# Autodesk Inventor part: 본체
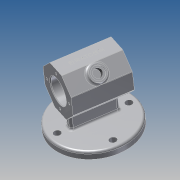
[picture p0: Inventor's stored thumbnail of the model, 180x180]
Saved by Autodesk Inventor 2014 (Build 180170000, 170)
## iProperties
Created: 2021-02
Part Number: 본체
Material: 알루미늄 6061
Document SubType Name: Modeling
Designer: kb542-22
Density: 2.71 g/cm^3
Appearance: 알루미늄 - 평지
Mass: 558.374 g
Surface Area: 514.422 cm^2
Volume: 206.042 cm^3
Author: kb542-22
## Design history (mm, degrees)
sketch "스케치1" dims "d9" = 58
  geometry: L1 (29, -12.012)-(12.012, -29); L2 (12.012, -29)-(-12.012, -29); L3 (-12.012, -29)-(-29, -12.012); L4 (-29, -12.012)-(-29, 12.012); L5 (-29, 12.012)-(-12.012, 29); L6 (-12.012, 29)-(12.012, 29); L7 (12.012, 29)-(29, 12.012); L8 (29, 12.012)-(29, -12.012); 4 further points
  constraints: 16 end point, 2 vertical alignment, 1 coincident, 1 horizontal alignment, 1 midpoint, 1 vertical, 20 other
extrude "돌출1" new body sketch "스케치1" stored distance "d10" = 70; taper "d11" = 0 deg
sketch "스케치2"
  geometry: L1 (12.012, 35)-(12.012, -35) reference; L2 (-12.012, 35)-(12.012, 35) reference; L3 (-12.012, 35)-(-12.012, -35) reference; L4 (12.012, -35)-(-12.012, -35) reference; L5 (0, 35)-(0, -35); L6 (0, 35)-(16, 35); L7 (16, 35)-(16, 23.3); L8 (15.7, 23)-(14, 23); L9 (14, 23)-(14, 20); L10 (14, 20)-(22, 20); L11 (22, 20)-(22, -20); L12 (22, -20)-(14, -20); L13 (14, -20)-(14, -23); L14 (14, -23)-(15.7, -23); L15 (16, -23.3)-(16, -35); L16 (16, -35)-(0, -35); A1 r 0.3 centre (15.7, 23.3) between (15.7, 23) and (16, 23.3); A2 r 0.3 centre (15.7, -23.3) between (16, -23.3) and (15.7, -23); 2 further points
  constraints: 24 end point, 6 perpendicular, 4 parallel, 4 point on circle, 4 tangent, 3 point on line, 2 centre point, 2 midpoint, 1 collinear, 1 equal radius
  dimensions: "d12" = 12 distance from line of point (16, 23) L6; "d13" = 12 distance between parallel lines of L16 L14; "d14" = 28 diameter of L9 L5; "d15" = 44 diameter of L11 L5; "d16" = 32 diameter of L7 L5; "d17" = 28 diameter of L13 L5; "d18" = 32 diameter of L15 L5; "d19" = 40 distance between parallel lines of L12 L10; "d20" = 3 distance between parallel lines of L10 L8 (derived); "d21" = 0.3 radius of A1
revolve "회전1" sketch "스케치2" stored, may be unused: angle "d22" = 90 deg
sketch "스케치3" dims "d23" = 46
  geometry: C1 r 16 at (0, 0) reference; 2 further points
  constraints: 2 vertical alignment, 1 coincident, 2 other
hole "구멍1" sketch "스케치3" at (0, 23) diameter "d24" = 3.242; stored, may be unused: countersink angle "d28" = 90 deg, drill point angle "d30" = 118 deg; dims "d25" = 8, "d26" = 4, "d27" = 2, "d29" = 10
sketch "스케치4"
  geometry: L1 (0, 0)-(0, 44.719); L2 (0, 0)-(24.042, 24.042); L3 (12.012, 29)-(29, 12.012) reference; C1 r 16 at (0, 0) reference; 1 further point
  constraints: 4 end point, 1 vertical
  dimensions: "d34" = 45 deg angle of L2 L1; "d35" = 5 distance from line of L3 L2.end
node "작업 평면1"
sketch "스케치5"
  geometry: C1 r 10 at (0, 0); 1 further point
  constraints: 1 centre point, 1 coincident
  dimensions: "d36" = 20 diameter of C1
extrude "돌출2" join sketch "스케치5" stored distance "d37" = 70; taper "d38" = 0 deg
node "작업 평면2"
sketch "스케치6"
  geometry: L1 (-29, 35)-(-29, -35) reference; L2 (29, 35)-(29, -35) reference; L3 (12.012, -35)-(-12.012, -35) reference; L4 (-12.012, 35)-(12.012, 35) reference; C1 r 52 at (0, 0); C2 r 4.5 at (-41, 0); C3 r 4.5 at (0, 41); C4 r 4.5 at (0, -41); C5 r 4.5 at (41, 0); A1 r 41 centre (0, 0) between (-41, 0) and (0, 41); 1 further point
  constraints: 6 centre point, 4 point on circle, 3 equal radius, 2 coincident, 2 horizontal alignment, 2 vertical alignment
  dimensions: "d40" = 104 diameter of C1; "d41" = 82 diameter of A1; "d42" = 9 diameter of C4
extrude "돌출3" join sketch "스케치6" distance "d43" = 10; taper "d44" = 0 deg
sketch "스케치7"
  geometry: L1 (28, -5)-(-28, -5); L2 (-28, -5)-(-28, 5); L3 (-28, 5)-(28, 5); L4 (28, 5)-(28, -5); L5 (-35, 12.012)-(35, 12.012) reference; L6 (-35, -12.012)-(-35, 12.012) reference; L7 (35, -12.012)-(-35, -12.012) reference; L8 (35, 12.012)-(35, -12.012) reference; C1 r 52 at (0, 0) reference; 2 further points
  constraints: 8 end point, 2 midpoint, 2 parallel, 1 horizontal, 1 horizontal alignment, 1 perpendicular, 1 vertical alignment
  dimensions: "d45" = 10 distance between parallel lines of L3 L1; "d46" = 56 distance between parallel lines of L4 L2
extrude "돌출4" join sketch "스케치7" stored distance "d47" = 10; taper "d48" = 0 deg
hole "구멍2" diameter "d51" = 10.917; stored, may be unused: countersink angle "d55" = 90 deg, drill point angle "d57" = 0 deg; dims "d49" = 10, "d50" = 10, "d52" = 8, "d53" = 16, "d54" = 2, "d56" = 10
node "작업 평면3"
sketch "스케치8"
  geometry: L1 (70, 0)-(0, 0) reference; L2 (70, 24.024)-(70, 0) reference; L3 (0, -16.988)-(70, -16.988) reference; 2 further points
  constraints: 1 other
  dimensions: "d59" = 35 distance from line of L2 point (35, 12.405); "d60" = 29 distance from line of L3 point (35, 12.012) (derived)
feature "엠보싱1" sketch "스케치8" dims "d9" = 58, "d12" = 12, "d13" = 12, "d14" = 28, "d15" = 44, "d16" = 32, "d17" = 28, "d18" = 32, "d19" = 40, "d20" = 3 (derived), "d21" = 0.3, "d61" = 0.5, "d62" = 0
fillet "모깎기1" dims "d63" = 3
fillet "모깎기2" dims "d64" = 3, "d68" = 1
chamfer "모따기1" distance "d65" = 1; stored, may be unused: second distance "d66" = 2, angle "d67" = 45 deg
node "솔리드1"
pattern_circular "원형 패턴1" dims angle "d32" = 360 deg
mirror "대칭1"
node "투영된 루프1"
node "투영된 루프2"
other parameters: "d39" = -62, "d58" = 33
